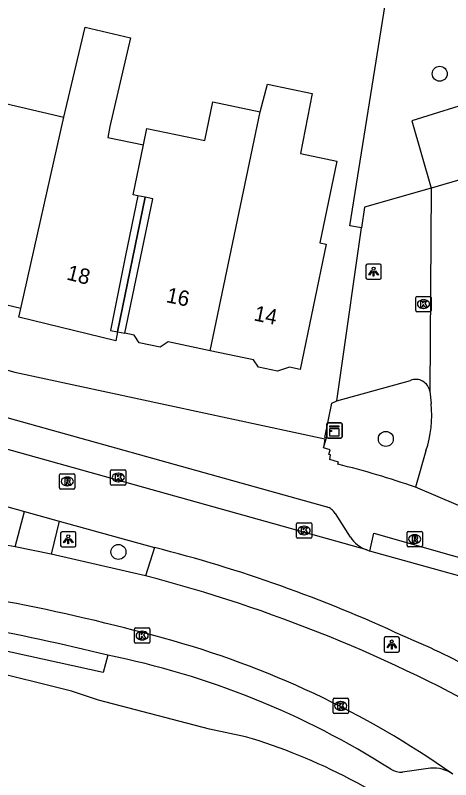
# Model space of a CAD drawing. Extents: x 158087 to 159494, y 382905 to 383981.
# Drawn here: x 158921.69 to 158950.15, y 383259.48 to 383309.41 of the extents above; entities that cross this region are included whole.
import ezdxf

# ---------------------------------------------------------------- set-up
doc = ezdxf.new("R2010")
doc.units = 0
for name, color, linetype in [('IMGEO_Berm_gesloten', 7, 'Continuous'), ('IMGEO_Boom', 7, 'Continuous'), ('IMGEO_Groenvoorziening', 7, 'Continuous'), ('IMGEO_Kast', 7, 'Continuous'), ('IMGEO_Kolk', 7, 'Continuous'), ('IMGEO_Lichtpunt', 7, 'Continuous'), ('IMGEO_Pand', 7, 'Continuous'), ('IMGEO_Pand_nummerreeks', 7, 'Continuous'), ('IMGEO_Pand_overbouw', 7, 'Continuous'), ('IMGEO_Parkeervlak_open', 7, 'Continuous'), ('IMGEO_Rijbaan_lokaal_gesloten', 7, 'Continuous'), ('IMGEO_Rijbaan_lokaal_open', 7, 'Continuous'), ('IMGEO_Rioolput', 7, 'Continuous'), ('IMGEO_Voetpad_open', 7, 'Continuous')]:
    doc.layers.add(name, color=color, linetype=linetype)

msp = doc.modelspace()

# ---------------------------------------------------------------- linework, layer by layer
at = {"layer": 'IMGEO_Berm_gesloten'}
msp.add_lwpolyline([(158930.801, 383274.642), (158930.207, 383272.795)], dxfattribs=at)
at = {"layer": 'IMGEO_Boom'}
for centre in [(158949.432, 383305.587), (158945.91, 383281.738), (158928.438, 383274.354)]:
    msp.add_circle(centre, 0.489, dxfattribs=at)
at = {"layer": 'IMGEO_Groenvoorziening'}
for points in [[(158944.329, 383295.526), (158943.553, 383295.646), (158947.075, 383317.609), (158947.158, 383318.125)], [(158941.836, 383281.15), (158942.032, 383281.814), (158941.927, 383281.836), (158942.379, 383284.081), (158942.709, 383284.22)]]:
    msp.add_lwpolyline(points, dxfattribs=at)
at = {"layer": 'IMGEO_Kast'}
for p, q in [((158942.123, 383282.794), (158942.964, 383282.794)), ((158942.964, 383282.794), (158942.123, 383282.794)), ((158942.048, 383281.869), (158942.048, 383282.71)), ((158942.048, 383282.71), (158942.048, 383281.869)), ((158943.048, 383282.719), (158943.048, 383281.878)), ((158943.048, 383281.878), (158943.048, 383282.719)), ((158942.973, 383281.794), (158942.132, 383281.794)), ((158942.132, 383281.794), (158942.973, 383281.794))]:
    msp.add_line(p, q, dxfattribs=at)
for points in [[(158942.243, 383282.584), (158942.843, 383282.584), (158942.843, 383282.499), (158942.243, 383282.499), (158942.243, 383282.584)], [(158942.243, 383282.409), (158942.843, 383282.409), (158942.843, 383281.92), (158942.243, 383281.92), (158942.243, 383282.409)]]:
    msp.add_lwpolyline(points, dxfattribs=at)
msp.add_circle((158942.327, 383282.258), 0.0377, dxfattribs=at)
for centre, start, end in [((158942.126, 383282.716), 92.4484, 184.2845), ((158942.126, 383282.716), 92.4484, 184.2845), ((158942.97, 383282.716), 2.4484, 94.2845), ((158942.97, 383282.716), 2.4484, 94.2845), ((158942.126, 383281.872), 182.4484, 274.2845), ((158942.126, 383281.872), 182.4484, 274.2845), ((158942.97, 383281.872), 272.4484, 4.2845), ((158942.97, 383281.872), 272.4484, 4.2845)]:
    msp.add_arc(centre, 0.0779, start, end, dxfattribs=at)
at = {"layer": 'IMGEO_Kolk'}
for p, q in [((158947.872, 383290.118), (158947.872, 383290.97)), ((158947.947, 383291.044), (158948.799, 383291.044)), ((158948.36, 383290.824), (158948.385, 383290.824)), ((158948.873, 383290.97), (158948.873, 383290.118)), ((158948.383, 383290.264), (158948.358, 383290.264)), ((158948.799, 383290.044), (158947.947, 383290.044)), ((158927.925, 383278.792), (158927.925, 383279.644)), ((158928, 383279.718), (158928.852, 383279.718)), ((158928.413, 383279.498), (158928.438, 383279.498)), ((158928.926, 383279.644), (158928.926, 383278.792)), ((158928.436, 383278.938), (158928.411, 383278.938)), ((158928.852, 383278.718), (158928, 383278.718)), ((158940.144, 383276.257), (158940.996, 383276.257)), ((158940.069, 383275.331), (158940.069, 383276.183)), ((158940.557, 383276.037), (158940.582, 383276.037)), ((158941.07, 383276.183), (158941.07, 383275.331)), ((158940.996, 383275.257), (158940.144, 383275.257)), ((158940.58, 383275.477), (158940.555, 383275.477)), ((158929.485, 383268.465), (158929.485, 383269.317)), ((158929.56, 383269.391), (158930.412, 383269.391)), ((158930.486, 383269.317), (158930.486, 383268.465)), ((158929.973, 383269.171), (158929.998, 383269.171)), ((158930.412, 383268.391), (158929.56, 383268.391)), ((158929.996, 383268.611), (158929.971, 383268.611)), ((158942.534, 383264.797), (158943.386, 383264.797)), ((158942.459, 383263.871), (158942.459, 383264.723)), ((158942.947, 383264.577), (158942.972, 383264.577)), ((158943.46, 383264.723), (158943.46, 383263.871)), ((158943.386, 383263.797), (158942.534, 383263.797)), ((158942.97, 383264.017), (158942.945, 383264.017))]:
    msp.add_line(p, q, dxfattribs=at)
for points in [[(158947.872, 383290.118), (158947.872, 383290.97)], [(158947.947, 383291.044), (158948.799, 383291.044)], [(158948.193, 383290.744), (158948.316, 383290.744), (158948.316, 383290.593), (158948.446, 383290.744), (158948.61, 383290.744), (158948.464, 383290.593), (158948.617, 383290.344), (158948.465, 383290.344), (158948.38, 383290.508), (158948.316, 383290.441), (158948.316, 383290.344), (158948.193, 383290.344), (158948.193, 383290.744)], [(158948.873, 383290.97), (158948.873, 383290.118)], [(158948.799, 383290.044), (158947.947, 383290.044)], [(158927.925, 383278.792), (158927.925, 383279.644)], [(158928, 383279.718), (158928.852, 383279.718)], [(158928.246, 383279.418), (158928.369, 383279.418), (158928.369, 383279.267), (158928.499, 383279.418), (158928.663, 383279.418), (158928.517, 383279.267), (158928.67, 383279.018), (158928.518, 383279.018), (158928.433, 383279.182), (158928.369, 383279.115), (158928.369, 383279.018), (158928.246, 383279.018), (158928.246, 383279.418)], [(158928.926, 383279.644), (158928.926, 383278.792)], [(158928.852, 383278.718), (158928, 383278.718)], [(158940.144, 383276.257), (158940.996, 383276.257)], [(158940.069, 383275.331), (158940.069, 383276.183)], [(158940.39, 383275.957), (158940.513, 383275.957), (158940.513, 383275.806), (158940.643, 383275.957), (158940.807, 383275.957), (158940.661, 383275.806), (158940.814, 383275.557), (158940.662, 383275.557), (158940.577, 383275.721), (158940.513, 383275.654), (158940.513, 383275.557), (158940.39, 383275.557), (158940.39, 383275.957)], [(158941.07, 383276.183), (158941.07, 383275.331)], [(158940.996, 383275.257), (158940.144, 383275.257)], [(158929.485, 383268.465), (158929.485, 383269.317)], [(158929.56, 383269.391), (158930.412, 383269.391)], [(158930.486, 383269.317), (158930.486, 383268.465)], [(158929.806, 383269.091), (158929.929, 383269.091), (158929.929, 383268.94), (158930.059, 383269.091), (158930.223, 383269.091), (158930.077, 383268.94), (158930.23, 383268.691), (158930.078, 383268.691), (158929.993, 383268.855), (158929.929, 383268.788), (158929.929, 383268.691), (158929.806, 383268.691), (158929.806, 383269.091)], [(158930.412, 383268.391), (158929.56, 383268.391)], [(158942.534, 383264.797), (158943.386, 383264.797)], [(158942.459, 383263.871), (158942.459, 383264.723)], [(158942.78, 383264.497), (158942.903, 383264.497), (158942.903, 383264.346), (158943.033, 383264.497), (158943.197, 383264.497), (158943.051, 383264.346), (158943.204, 383264.097), (158943.052, 383264.097), (158942.967, 383264.261), (158942.903, 383264.194), (158942.903, 383264.097), (158942.78, 383264.097), (158942.78, 383264.497)], [(158943.46, 383264.723), (158943.46, 383263.871)], [(158943.386, 383263.797), (158942.534, 383263.797)]]:
    msp.add_lwpolyline(points, dxfattribs=at)
for centre, start, end in [((158947.949, 383290.968), 91.552, 178.448), ((158947.949, 383290.968), 91.552, 178.448), ((158948.797, 383290.968), 1.552, 88.448), ((158948.797, 383290.968), 1.552, 88.448), ((158947.949, 383290.12), 181.552, 268.448), ((158947.949, 383290.12), 181.552, 268.448), ((158948.797, 383290.12), 271.552, 358.448), ((158948.797, 383290.12), 271.552, 358.448), ((158928.002, 383279.642), 91.552, 178.448), ((158928.002, 383279.642), 91.552, 178.448), ((158928.85, 383279.642), 1.552, 88.448), ((158928.85, 383279.642), 1.552, 88.448), ((158928.002, 383278.794), 181.552, 268.448), ((158928.002, 383278.794), 181.552, 268.448), ((158928.85, 383278.794), 271.552, 358.448), ((158928.85, 383278.794), 271.552, 358.448), ((158940.146, 383276.181), 91.552, 178.448), ((158940.146, 383276.181), 91.552, 178.448), ((158940.994, 383276.181), 1.552, 88.448), ((158940.994, 383276.181), 1.552, 88.448), ((158940.146, 383275.333), 181.552, 268.448), ((158940.146, 383275.333), 181.552, 268.448), ((158940.994, 383275.333), 271.552, 358.448), ((158940.994, 383275.333), 271.552, 358.448), ((158929.562, 383269.315), 91.552, 178.448), ((158929.562, 383269.315), 91.552, 178.448), ((158930.41, 383269.315), 1.552, 88.448), ((158930.41, 383269.315), 1.552, 88.448), ((158929.562, 383268.467), 181.552, 268.448), ((158929.562, 383268.467), 181.552, 268.448), ((158930.41, 383268.467), 271.552, 358.448), ((158930.41, 383268.467), 271.552, 358.448), ((158942.536, 383264.721), 91.552, 178.448), ((158942.536, 383264.721), 91.552, 178.448), ((158943.384, 383264.721), 1.552, 88.448), ((158943.384, 383264.721), 1.552, 88.448), ((158942.536, 383263.873), 181.552, 268.448), ((158942.536, 383263.873), 181.552, 268.448), ((158943.384, 383263.873), 271.552, 358.448), ((158943.384, 383263.873), 271.552, 358.448)]:
    msp.add_arc(centre, 0.0765, start, end, dxfattribs=at)
for centre, major_axis, ratio, start_param, end_param in [((158948.359, 383290.544), (-0.387, 0.002), 0.722429, 4.712389, 7.853982), ((158948.384, 383290.544), (-0.39, 0.002), 0.717154, 1.570796, 4.712389), ((158928.412, 383279.218), (-0.387, 0.002), 0.722429, 4.712389, 7.853982), ((158928.437, 383279.218), (-0.39, 0.002), 0.717154, 1.570796, 4.712389), ((158940.556, 383275.757), (-0.387, 0.002), 0.722429, 4.712389, 7.853982), ((158940.581, 383275.757), (-0.39, 0.002), 0.717154, 1.570796, 4.712389), ((158929.972, 383268.891), (-0.387, 0.002), 0.722429, 4.712389, 7.853982), ((158929.997, 383268.891), (-0.39, 0.002), 0.717154, 1.570796, 4.712389), ((158942.946, 383264.297), (-0.387, 0.002), 0.722429, 4.712389, 7.853982), ((158942.971, 383264.297), (-0.39, 0.002), 0.717154, 1.570796, 4.712389)]:
    msp.add_ellipse(centre, major_axis=major_axis, ratio=ratio, start_param=start_param, end_param=end_param, dxfattribs=at)
at = {"layer": 'IMGEO_Lichtpunt'}
for p, q in [((158944.61, 383293.063), (158944.61, 383292.256)), ((158944.61, 383293.063), (158944.61, 383292.256)), ((158945.512, 383293.158), (158944.704, 383293.158)), ((158945.512, 383293.158), (158944.704, 383293.158)), ((158945.606, 383292.256), (158945.606, 383293.063)), ((158945.606, 383292.256), (158945.606, 383293.063)), ((158944.704, 383292.162), (158945.512, 383292.162)), ((158944.704, 383292.162), (158945.512, 383292.162)), ((158924.657, 383275.581), (158924.657, 383274.774)), ((158924.657, 383275.581), (158924.657, 383274.774)), ((158925.559, 383275.676), (158924.751, 383275.676)), ((158925.559, 383275.676), (158924.751, 383275.676)), ((158925.653, 383274.774), (158925.653, 383275.581)), ((158925.653, 383274.774), (158925.653, 383275.581)), ((158924.751, 383274.68), (158925.559, 383274.68)), ((158924.751, 383274.68), (158925.559, 383274.68)), ((158946.703, 383268.803), (158945.895, 383268.803)), ((158946.703, 383268.803), (158945.895, 383268.803)), ((158945.801, 383268.708), (158945.801, 383267.901)), ((158945.801, 383268.708), (158945.801, 383267.901)), ((158946.797, 383267.901), (158946.797, 383268.708)), ((158946.797, 383267.901), (158946.797, 383268.708)), ((158945.895, 383267.807), (158946.703, 383267.807)), ((158945.895, 383267.807), (158946.703, 383267.807))]:
    msp.add_line(p, q, dxfattribs=at)
for points in [[(158944.984, 383292.727), (158945.023, 383292.699), (158944.835, 383292.437), (158944.797, 383292.464), (158944.984, 383292.727)], [(158945.086, 383292.679), (158945.133, 383292.679), (158945.133, 383292.357), (158945.086, 383292.357), (158945.086, 383292.679)], [(158945.196, 383292.699), (158945.234, 383292.726), (158945.421, 383292.464), (158945.382, 383292.436), (158945.196, 383292.699)], [(158925.031, 383275.245), (158925.07, 383275.217), (158924.882, 383274.955), (158924.844, 383274.982), (158925.031, 383275.245)], [(158925.133, 383275.197), (158925.18, 383275.197), (158925.18, 383274.875), (158925.133, 383274.875), (158925.133, 383275.197)], [(158925.243, 383275.217), (158925.281, 383275.244), (158925.468, 383274.982), (158925.429, 383274.954), (158925.243, 383275.217)], [(158946.175, 383268.372), (158946.214, 383268.344), (158946.026, 383268.082), (158945.988, 383268.109), (158946.175, 383268.372)], [(158946.277, 383268.324), (158946.324, 383268.324), (158946.324, 383268.002), (158946.277, 383268.002), (158946.277, 383268.324)], [(158946.387, 383268.344), (158946.425, 383268.371), (158946.612, 383268.109), (158946.573, 383268.081), (158946.387, 383268.344)]]:
    msp.add_lwpolyline(points, dxfattribs=at)
for centre in [(158945.109, 383292.861), (158925.156, 383275.379), (158946.3, 383268.506)]:
    msp.add_circle(centre, 0.0994, dxfattribs=at)
for centre, start, end in [((158944.704, 383293.063), 90, 180), ((158944.704, 383293.063), 90, 180), ((158945.512, 383293.063), 0, 90), ((158945.512, 383293.063), 0, 90), ((158944.704, 383292.256), 180, 270), ((158944.704, 383292.256), 180, 270), ((158945.512, 383292.256), 270, 0), ((158945.512, 383292.256), 270, 360), ((158924.751, 383275.581), 90, 180), ((158924.751, 383275.581), 90, 180), ((158925.559, 383275.581), 0, 90), ((158925.559, 383275.581), 0, 90), ((158924.751, 383274.774), 180, 270), ((158924.751, 383274.774), 180, 270), ((158925.559, 383274.774), 270, 0), ((158925.559, 383274.774), 270, 360), ((158945.895, 383268.708), 90, 180), ((158945.895, 383268.708), 90, 180), ((158946.703, 383268.708), 0, 90), ((158946.703, 383268.708), 0, 90), ((158945.895, 383267.901), 180, 270), ((158945.895, 383267.901), 180, 270), ((158946.703, 383267.901), 270, 0), ((158946.703, 383267.901), 270, 360)]:
    msp.add_arc(centre, 0.0946, start, end, dxfattribs=at)
at = {"layer": 'IMGEO_Pand'}
for points in [[(158924.872, 383302.745), (158926.251, 383308.626), (158929.231, 383307.927), (158927.875, 383302.144), (158927.741, 383301.419), (158930.065, 383300.935)], [(158937.7, 383303.109), (158938.169, 383304.907), (158941.105, 383304.294), (158940.334, 383300.368), (158942.717, 383299.871), (158941.603, 383294.535), (158942.014, 383294.449), (158940.31, 383286.274), (158939.625, 383286.417), (158938.827, 383286.154), (158937.587, 383286.413), (158937.263, 383286.907), (158934.431, 383287.497)], [(158922.056, 383290.247), (158919.751, 383290.807), (158919.255, 383290.511), (158917.247, 383291.019), (158917.097, 383291.549), (158916.642, 383291.665), (158917.868, 383296.513), (158918.718, 383299.875), (158918.394, 383300.632), (158919.261, 383304.061), (158924.872, 383302.745)], [(158930.065, 383300.935), (158930.289, 383302.009), (158934.084, 383301.219), (158934.612, 383303.752), (158937.7, 383303.109)], [(158922.056, 383290.247), (158924.872, 383302.745)], [(158934.431, 383287.497), (158937.7, 383303.109)], [(158929.695, 383297.622), (158929.389, 383297.686), (158930.065, 383300.935)], [(158929.695, 383297.622), (158928.904, 383293.726), (158927.909, 383288.825), (158928.379, 383288.738), (158928.256, 383288.142), (158921.928, 383289.68), (158922.056, 383290.247)], [(158934.431, 383287.497), (158931.677, 383288.071), (158931.162, 383287.733), (158929.8, 383288.017), (158929.469, 383288.521), (158928.848, 383288.651), (158929.868, 383293.546), (158930.674, 383297.418), (158930.185, 383297.52), (158929.695, 383297.622)]]:
    msp.add_lwpolyline(points, dxfattribs=at)
at = {"layer": 'IMGEO_Pand_overbouw'}
for points in [[(158927.909, 383288.825), (158928.379, 383288.738), (158930.185, 383297.52), (158929.695, 383297.622), (158928.904, 383293.726)], [(158928.848, 383288.651), (158929.868, 383293.546), (158930.674, 383297.418), (158930.185, 383297.52), (158928.379, 383288.738)]]:
    msp.add_lwpolyline(points, close=True, dxfattribs=at)
at = {"layer": 'IMGEO_Parkeervlak_open'}
for points in [[(158952.077, 383303.899), (158947.612, 383302.509), (158948.864, 383298.116)], [(158948.864, 383298.116), (158944.523, 383296.879), (158944.329, 383295.526)], [(158942.709, 383284.22), (158942.949, 383285.896), (158944.329, 383295.526)], [(158942.709, 383284.22), (158947.515, 383285.552)]]:
    msp.add_lwpolyline(points, dxfattribs=at)
msp.add_arc((158947.871, 383284.694), 0.929, 10.127, 112.5321, dxfattribs=at)
at = {"layer": 'IMGEO_Rijbaan_lokaal_gesloten'}
for points in [[(158944.658, 383274.49), (158890.262, 383289.69), (158765.072, 383325.196), (158741.506, 383331.88)], [(158907.118, 383281.238), (158922.301, 383276.989)], [(158922.301, 383276.989), (158924.571, 383276.356)], [(158924.571, 383276.356), (158930.801, 383274.642)], [(158924.029, 383274.209), (158921.694, 383274.686)], [(158944.658, 383274.49), (158944.862, 383274.414)], [(158952.399, 383272.308), (158944.862, 383274.414)], [(158930.207, 383272.795), (158924.029, 383274.209)]]:
    msp.add_lwpolyline(points, dxfattribs=at)
for centre, radius, start, end in [((158875.774, 383057.544), 221.944, 78.05942, 82.11522), ((158907.986, 383184.783), 92.71, 65.10568, 75.75379), ((158906.245, 383180.279), 95.568, 60.32178, 75.47946), ((158897.297, 383145.272), 128.068, 74.56509, 79.28019), ((158926.513, 383219.723), 53.259, 61.6971, 67.3631), ((158915.329, 383209.947), 60.927, 54.98499, 74.72402)]:
    msp.add_arc(centre, radius, start, end, dxfattribs=at)
at = {"layer": 'IMGEO_Rijbaan_lokaal_open'}
for points in [[(158955.706, 383300.11), (158948.958, 383298.143), (158948.864, 383298.116)], [(158948.864, 383298.116), (158948.786, 383284.857)], [(158948.786, 383284.857), (158948.87, 383284.047)], [(158948.532, 383280.956), (158947.842, 383278.581)], [(158952.012, 383276.755), (158950.654, 383277.399), (158947.842, 383278.581)]]:
    msp.add_lwpolyline(points, dxfattribs=at)
msp.add_arc((158941.76, 383283.26), 7.153, 341.206, 6.313, dxfattribs=at)
at = {"layer": 'IMGEO_Rioolput'}
for p, q in [((158924.592, 383278.536), (158924.592, 383279.388)), ((158924.667, 383279.462), (158925.519, 383279.462)), ((158925.593, 383279.388), (158925.593, 383278.536)), ((158925.08, 383279.242), (158925.105, 383279.242)), ((158925.519, 383278.462), (158924.667, 383278.462)), ((158925.103, 383278.682), (158925.078, 383278.682)), ((158947.297, 383274.767), (158947.297, 383275.619)), ((158947.372, 383275.693), (158948.224, 383275.693)), ((158947.785, 383275.473), (158947.81, 383275.473)), ((158948.298, 383275.619), (158948.298, 383274.767)), ((158947.808, 383274.913), (158947.783, 383274.913)), ((158948.224, 383274.693), (158947.372, 383274.693))]:
    msp.add_line(p, q, dxfattribs=at)
for points in [[(158924.592, 383278.536), (158924.592, 383279.388)], [(158924.667, 383279.462), (158925.519, 383279.462)], [(158925.593, 383279.388), (158925.593, 383278.536)], [(158925.181, 383279.16), (158924.929, 383279.162), (158924.929, 383278.762)], [(158924.929, 383278.762), (158925.053, 383278.762), (158925.053, 383278.924), (158925.064, 383278.924)], [(158925.107, 383279.081), (158925.053, 383279.081), (158925.053, 383279)], [(158925.053, 383279), (158925.105, 383279)], [(158925.111, 383278.895), (158925.182, 383278.762), (158925.322, 383278.762), (158925.257, 383278.888)], [(158925.519, 383278.462), (158924.667, 383278.462)], [(158947.297, 383274.767), (158947.297, 383275.619)], [(158947.372, 383275.693), (158948.224, 383275.693)], [(158947.886, 383275.391), (158947.634, 383275.393), (158947.634, 383274.993)], [(158947.812, 383275.312), (158947.758, 383275.312), (158947.758, 383275.231)], [(158948.298, 383275.619), (158948.298, 383274.767)], [(158947.634, 383274.993), (158947.758, 383274.993), (158947.758, 383275.155), (158947.769, 383275.155)], [(158947.758, 383275.231), (158947.81, 383275.231)], [(158947.816, 383275.126), (158947.887, 383274.993), (158948.027, 383274.993), (158947.962, 383275.119)], [(158948.224, 383274.693), (158947.372, 383274.693)]]:
    msp.add_lwpolyline(points, dxfattribs=at)
for centre, radius, start, end in [((158924.669, 383279.386), 0.0765, 91.552, 178.448), ((158924.669, 383279.386), 0.0765, 91.552, 178.448), ((158925.517, 383279.386), 0.0765, 1.552, 88.448), ((158925.517, 383279.386), 0.0765, 1.552, 88.448), ((158925.063, 383278.871), 0.0533, 26.0293, 88.6989), ((158925.089, 383279.189), 0.19, 274.7715, 282.9687), ((158925.113, 383278.985), 0.0964, 77.0061, 93.1865), ((158925.127, 383279.042), 0.0378, 276.6634, 79.6772), ((158925.18, 383279.05), 0.109, 350.3612, 89.416), ((158925.178, 383279.05), 0.112, 277.5842, 350.9817), ((158925.162, 383278.835), 0.108, 29.5134, 73.7905), ((158924.669, 383278.538), 0.0765, 181.552, 268.448), ((158924.669, 383278.538), 0.0765, 181.552, 268.448), ((158925.517, 383278.538), 0.0765, 271.552, 358.448), ((158925.517, 383278.538), 0.0765, 271.552, 358.448), ((158947.374, 383275.617), 0.0765, 91.552, 178.448), ((158947.374, 383275.617), 0.0765, 91.552, 178.448), ((158947.818, 383275.216), 0.0964, 77.0061, 93.1865), ((158947.832, 383275.273), 0.0378, 276.6634, 79.6772), ((158947.885, 383275.281), 0.109, 350.3612, 89.416), ((158947.883, 383275.281), 0.112, 277.5842, 350.9817), ((158948.222, 383275.617), 0.0765, 1.552, 88.448), ((158948.222, 383275.617), 0.0765, 1.552, 88.448), ((158947.374, 383274.769), 0.0765, 181.552, 268.448), ((158947.374, 383274.769), 0.0765, 181.552, 268.448), ((158947.768, 383275.102), 0.0533, 26.0293, 88.6989), ((158947.794, 383275.42), 0.19, 274.7715, 282.9687), ((158947.867, 383275.066), 0.108, 29.5134, 73.7905), ((158948.222, 383274.769), 0.0765, 271.552, 358.448), ((158948.222, 383274.769), 0.0765, 271.552, 358.448)]:
    msp.add_arc(centre, radius, start, end, dxfattribs=at)
for centre, major_axis, ratio, start_param, end_param in [((158925.079, 383278.962), (-0.387, 0.002), 0.722429, 4.712389, 7.853982), ((158925.104, 383278.962), (-0.39, 0.002), 0.717154, 1.570796, 4.712389), ((158947.784, 383275.193), (-0.387, 0.002), 0.722429, 4.712389, 7.853982), ((158947.809, 383275.193), (-0.39, 0.002), 0.717154, 1.570796, 4.712389)]:
    msp.add_ellipse(centre, major_axis=major_axis, ratio=ratio, start_param=start_param, end_param=end_param, dxfattribs=at)
at = {"layer": 'IMGEO_Voetpad_open'}
for points in [[(158769.481, 383325.984), (158890.831, 383291.584), (158942.057, 383277.301)], [(158830.055, 383312.009), (158909.214, 383289.555), (158921.656, 383286.099), (158941.914, 383281.737), (158941.836, 383281.15)], [(158942.772, 383280.083), (158942.813, 383280.22), (158942.252, 383280.399), (158942.298, 383280.691), (158942.189, 383280.727), (158942.264, 383281.024), (158941.836, 383281.15)], [(158921.694, 383274.686), (158922.301, 383276.989)], [(158942.603, 383276.866), (158943.59, 383275.33)], [(158924.571, 383276.356), (158924.029, 383274.209)], [(158944.862, 383274.414), (158945.135, 383275.585), (158952.713, 383273.426), (158952.399, 383272.308)], [(158927.733, 383267.61), (158927.448, 383266.482), (158918.585, 383268.414), (158918.858, 383269.54)], [(158936.744, 383262.28), (158934.385, 383262.791), (158927.129, 383264.682), (158925.371, 383265.27), (158919.563, 383266.705), (158904.778, 383269.155), (158904.001, 383266.212)], [(158948.832, 383260.238), (158946.992, 383259.962)]]:
    msp.add_lwpolyline(points, dxfattribs=at)
for centre, radius, start, end in [((158929.938, 383227.455), 54.17, 70.7004, 76.2955), ((158941.725, 383276.324), 1.032, 31.684, 71.2271), ((158945.409, 383276.543), 2.186, 213.711, 249.9177), ((158885.753, 383095.938), 176.731, 76.25879, 79.20362), ((158917.029, 383214.312), 54.362, 57.5085, 78.6443), ((158926.527, 383227.32), 36.423, 62.1042, 73.7094), ((158947.004, 383261.535), 1.573, 240.5682, 269.5596), ((158948.992, 383257.932), 2.312, 55.8989, 93.9642), ((158930.205, 383233.082), 29.615, 45.5681, 63.1773)]:
    msp.add_arc(centre, radius, start, end, dxfattribs=at)

# ---------------------------------------------------------------- texts
at = {"layer": 'IMGEO_Pand_nummerreeks'}
for s, rotation, p in [('18', 345.8537, (158924.998, 383292.158)), ('16', 348.283, (158931.506, 383290.674)), ('14', 348.284, (158937.236, 383289.485))]:
    msp.add_text(s, height=1, rotation=rotation, dxfattribs=at).set_placement(p)

doc.saveas('drawing.dxf')
